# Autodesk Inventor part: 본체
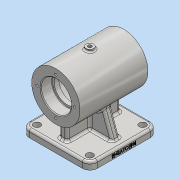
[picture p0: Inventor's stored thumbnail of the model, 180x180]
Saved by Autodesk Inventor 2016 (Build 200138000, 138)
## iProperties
Created: 2019-06
Part Number: 본체
Material: 알루미늄 6061
Document SubType Name: Modeling
Designer: Administrator
Density: 2.7 g/cm^3
Appearance: 알루미늄 - 평지
Mass: 685.637 g
Surface Area: 608.025 cm^2
Volume: 253.94 cm^3
Author: Administrator
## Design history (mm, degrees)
sketch "스케치1"
  geometry: L1 (-45, 45)-(45, 45); L2 (45, 45)-(45, -45); L3 (45, -45)-(-45, -45); L4 (-45, -45)-(-45, 45); L5 (-45, 45)-(45, -45); L6 (45, 45)-(-45, -45); 1 further point
  constraints: 12 end point, 2 midpoint, 2 parallel, 1 horizontal, 1 perpendicular
  dimensions: "d0" = 90 distance of L2.end L3.end; "d1" = 90 distance of L1.end L2.end
extrude "돌출1" new body sketch "스케치1" distance "d2" = 10; taper "d3" = 0 deg
sketch "스케치2" dims "d21" = 0
  geometry: L1 (-45, 65)-(45, 65); L2 (45, 0)-(-45, 0) reference; L3 (-45, 65)-(-45, 97); L4 (-45, 97)-(45, 97); L5 (45, 97)-(45, 65); 3 further points
  constraints: 8 end point, 2 midpoint, 2 perpendicular, 1 horizontal, 1 vertical, 1 vertical alignment
  dimensions: "d4" = 90 distance of L1.start L1.end; "d5" = 65 distance between parallel lines of L2 L1; "d6" = 64 diameter of L4 L1
revolve "회전1" sketch "스케치2" stored, may be unused: angle "d7" = 90 deg
sketch "스케치3"
  geometry: L1 (-45, 33)-(-45, 97) reference; L2 (-45, 65)-(45, 65); L3 (45, 33)-(45, 97) reference; L4 (-45, 65)-(-45, 85); L5 (-45, 85)-(-30, 85); L6 (-30, 85)-(-30, 82); L7 (-30, 82)-(-24, 82); L8 (-24, 82)-(-24, 90); L9 (-24, 90)-(24, 90); L10 (24, 90)-(24, 82); L11 (24, 82)-(30, 82); L12 (30, 82)-(30, 85); L13 (30, 85)-(45, 85); L14 (45, 85)-(45, 65); 1 further point
  constraints: 24 end point, 8 perpendicular, 2 midpoint, 2 point on line, 1 collinear, 1 vertical
  dimensions: "d8" = 15 distance of L4.end L5.end; "d9" = 6 distance of L6.end L7.end; "d10" = 48 distance of L8.end L9.end; "d11" = 6 distance of L10.end L11.end; "d12" = 40 diameter of L5 L2; "d13" = 34 diameter of L7 L2; "d14" = 50 diameter of L9 L2; "d15" = 34 diameter of L11 L2; "d16" = 40 diameter of L13 L2
revolve "회전2" sketch "스케치3" stored, may be unused: angle "d17" = 90 deg
sketch "스케치4"
  geometry: L1 (-5, -35)-(5, -35); L2 (5, -35)-(5, 35); L3 (5, 35)-(-5, 35); L4 (-5, 35)-(-5, -35); L5 (-5, -35)-(5, 35); L6 (5, -35)-(-5, 35); 1 further point
  constraints: 12 end point, 2 midpoint, 2 parallel, 1 horizontal, 1 perpendicular
  dimensions: "d18" = 10 distance of L3.end L2.end; "d19" = 70 distance of L2.end L1.end
extrude "돌출2" join sketch "스케치4" stored distance "d20" = 10; taper "d21" = 0 deg
sketch "스케치5"
  geometry: L1 (-35, 10)-(-23.058, 42.811); 2 further points
  constraints: 2 end point
feature "리브1" sketch "스케치5" dims "d24" = 1, "d25" = 10, "d26" = 0, "d27" = 0, "d28" = 1, "d29" = 1
sketch "스케치6"
  geometry: 2 further points
hole "구멍1" sketch "스케치6" at (0, 25) diameter "d31" = 3.242; stored, may be unused: countersink angle "d35" = 90 deg, drill point angle "d37" = 118 deg; dims "d32" = 7, "d33" = 4, "d34" = 2, "d36" = 9
fillet "모깎기1" dims "d41" = 10
fillet "모깎기2" dims "d42" = 3
hole "구멍2" diameter "d45" = 9; stored, may be unused: countersink angle "d49" = 90 deg, drill point angle "d51" = 118 deg; dims "d43" = 10, "d44" = 10, "d46" = 7, "d47" = 4, "d48" = 2, "d50" = 9
node "작업 평면1"
sketch "스케치7"
  geometry: C1 r 5 at (0, 0); 1 further point
  constraints: 1 centre point, 1 coincident
  dimensions: "d53" = 10 diameter of C1
extrude "돌출3" join sketch "스케치7" stored distance "d54" = 10; taper "d55" = 0 deg
hole "구멍3" diameter "d58" = 4.917; stored, may be unused: countersink angle "d62" = 90 deg, drill point angle "d64" = 0 deg; dims "d56" = 10, "d57" = 10, "d59" = 12, "d60" = 4, "d61" = 2, "d63" = 17.1
fillet "모깎기3" dims "d65" = 2
fillet "모깎기4" dims "d66" = 3
fillet "모깎기5" dims "d67" = 3
fillet "모깎기6" dims "d68" = 0.6
fillet "모깎기7" dims "d69" = 3
sketch "스케치8"
  geometry: L1 (0, 70)-(0, 0) reference; L2 (0, 80)-(-7, 80) reference; 2 further points
  constraints: 1 other
  dimensions: "d70" = 4 distance from line of L1 point (-4, 35); "d71" = 45 distance from line of L2 point (-4, 35)
feature "엠보싱1" sketch "스케치8" dims "d0" = 90, "d1" = 90, "d8" = 15, "d9" = 6, "d10" = 48, "d11" = 6, "d12" = 40, "d13" = 34, "d14" = 50, "d15" = 34, "d16" = 40, "d72" = 0.5, "d73" = 0
chamfer "모따기1" distance "d74" = 1; stored, may be unused: second distance "d75" = 2, angle "d76" = 45 deg
sketch "스케치9"
  geometry: L1 (-26.34, -40)-(26.34, -40); L2 (40, -22.155)-(40, 22.155); L3 (26.964, 40)-(-26.34, 40); L4 (-40, 22.155)-(-40, -22.155); L5 (-35, -45)-(35, -45) reference; L6 (0, 0)-(-10.585, 0); L7 (0, 0)-(0, 16.208); C1 r 4.5 at (-35, -35) reference; C2 r 4.5 at (35, -35) reference; C3 r 4.5 at (35, 35) reference; C4 r 4.5 at (-35, 35) reference; A1 r 10 centre (35, -35) between (36.538, -25.119) and (26.34, -40); A2 r 9.464 centre (35, 35) between (26.964, 40) and (36.456, 25.648); A3 r 10 centre (-35, 35) between (-36.538, 25.119) and (-26.34, 40); A4 r 3 centre (-37, -22.155) between (-40, -22.155) and (-36.538, -25.119); A5 r 3 centre (37, -22.155) between (36.538, -25.119) and (40, -22.155); A6 r 3 centre (-37, 22.155) between (-36.538, 25.119) and (-40, 22.155); A7 r 3 centre (37.051, 22.708) between (40, 22.155) and (36.456, 25.648); A8 r 10 centre (-35, -35) between (-26.34, -40) and (-36.538, -25.119)
  constraints: 16 point on circle, 12 end point, 8 centre point, 5 tangent, 3 coincident, 2 horizontal, 2 parallel, 1 perpendicular, 1 symmetric about line, 1 vertical, 1 other
  dimensions: "d78" = 10 radius of A1; "d80" = 10 radius of A3; "d84" = 5 distance between parallel lines of L5 L1; "d85" = 3 radius of A4; "d86" = 3 radius of A5; "d88" = 3 radius of A6; "d89" = 80 distance between parallel lines of L1 L3; "d90" = 80 distance between parallel lines of L4 L2
extrude "돌출4" cut sketch "스케치9" distance "d91" = 5; taper "d92" = 0 deg
fillet "모깎기8" dims "d93" = 3
fillet "모깎기9" dims "d94" = 3
node "솔리드1"
mirror "대칭1"
pattern_circular "원형 패턴1" dims angle "d39" = 360 deg
mirror "대칭2"
mirror "대칭3"
mirror "대칭4"
